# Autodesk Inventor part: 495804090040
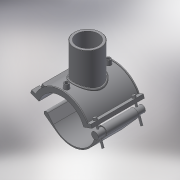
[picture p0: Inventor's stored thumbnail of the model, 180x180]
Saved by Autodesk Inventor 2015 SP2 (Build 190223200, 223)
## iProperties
Created: 2017-07
Part Number: 495804090040
Material: Generic
Description: PLASSON BRANCH SADDLE 90-40
Document SubType Name: Modeling
Designer: KIM
Density: 1 g/cm^3
Appearance: Default
Author: KIM
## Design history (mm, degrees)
derived "495804.ipt"
feature "Solid1::495804.ipt"
feature "Solid2::495804.ipt"
tag "TaggingFeature1"
body "Solid1"
body "Solid2"
other parameters: "d2" = 126, "d3" = 22.5, "d4" = 118, "d5" = 0, "d6" = 0.1, "d8" = 0, "d19" = 6, "d20" = 6, "d21" = 70.8, "d23" = 0, "d24" = 35.4, "d26" = 0, "d27" = 3, "d28" = 3, "d29" = 3, "d31" = 6, "d32" = 0, "d33" = 0, "d34" = 0.6, "d40" = 57.2, "d41" = 44, "d43" = 0, "d45" = 0, "d47" = 133, "d50" = 0, "d70" = 15, "d72" = 0, "d73" = 6, "d75" = 5, "d76" = 0, "d77" = 4.5, "d78" = 75, "d79" = 15, "d80" = 47.2, "d82" = 5 deg, "d84" = 4, "d85" = 14, "d86" = 0, "d87" = 3, "d88" = 0, "d89" = 1, "d90" = 1, "d91" = 94.4, "d92" = 0, "d93" = 0.5, "d94" = 47.36842, "d96" = 112.2, "d97" = 2.36, "d98" = 0, "d102" = 1.2, "d103" = 32, "d105" = 0, "d109" = -26, "d117" = 0.4, "d120" = 140 deg, "d121" = 24.228, "d122" = 20 deg, "d124" = 66, "d126" = 0, "d143" = 94.5, "d150" = 16.2, "d159" = 4, "d161" = 2.25, "d162" = 70.8, "d163" = 0, "d167" = 18, "d173" = 1, "d175" = 45, "d176" = 20 deg, "d177" = 6.3, "d180" = 0, "d185" = 38.35, "d186" = 38.35, "d187" = 55, "d188" = 6, "d189" = 6.3, "d190" = 0, "d191" = 82.5, "d202" = 0, "d216" = 106.2, "d217" = 0, "d221" = 43.66, "d222" = 6.3, "d223" = 3.78, "d224" = 45, "d225" = 3.78, "d227" = 12.96, "d230" = 55.8, "d236" = 20 deg, "d237" = 62, "d238" = 20 deg, "d239" = 6.3, "B_" = 126, "H_" = 78, "L_" = 118, "d_t" = 6, "H_1" = 68, "d148" = 2.25, "d160" = 2.25
